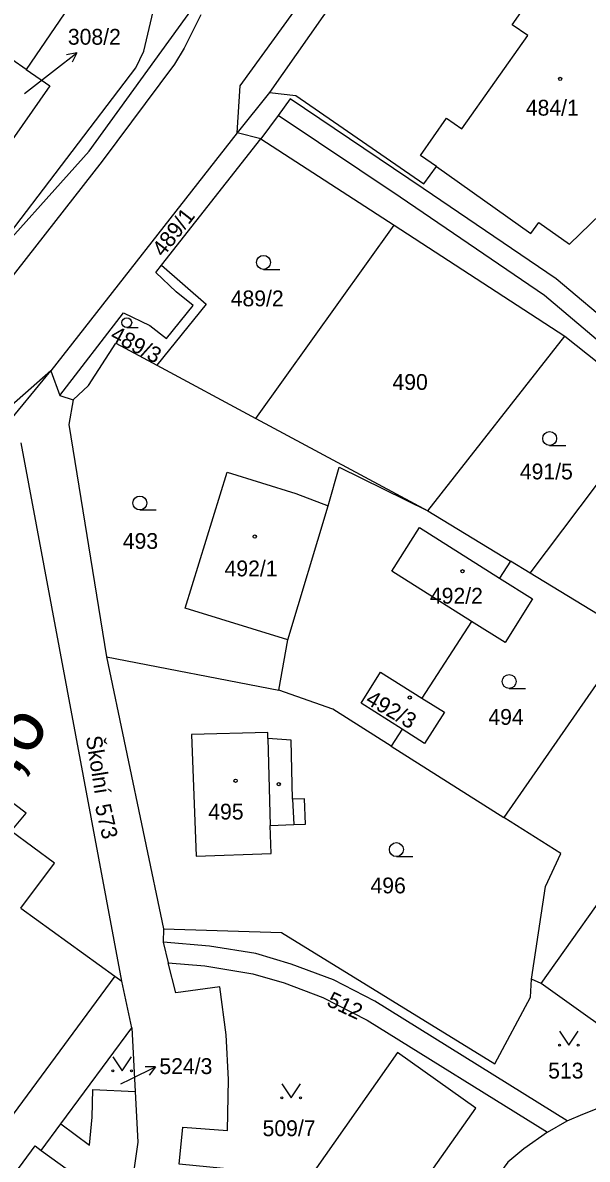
# Model space of a CAD drawing. Extents: x -558358 to -557517, y -1073786 to -1073189.
# Drawn here: x -558078.9 to -558018.3, y -1073467.9 to -1073345.8 of the extents above; entities that cross this region are included whole.
import ezdxf

# ---------------------------------------------------------------- set-up
doc = ezdxf.new("R2010")
doc.units = 0
for name, color, linetype in [('Hranice parcel', 7, 'Continuous'), ('Návěst místo trati', 7, 'Continuous'), ('Parcelní čísla', 7, 'Continuous'), ('Pop  PČ popisy', 7, 'Continuous'), ('Svazek obcí údolí Desné', 7, 'Continuous'), ('Vnitřní kresba', 7, 'Continuous'), ('Značky budov', 7, 'Continuous'), ('Značky kultur', 7, 'Continuous')]:
    doc.layers.add(name, color=color, linetype=linetype)

msp = doc.modelspace()

# ---------------------------------------------------------------- linework, layer by layer
at = {"layer": 'Hranice parcel'}
for p, q in [((-558028.41, -1073318.97), (-558052.39, -1073353.27)), ((-558055.85, -1073357.6), (-558055.56, -1073352.56)), ((-558052.39, -1073353.27), (-558055.85, -1073357.6)), ((-558051.46, -1073355.75), (-558053.32, -1073358.25)), ((-558055.85, -1073357.6), (-558075.89, -1073383.19)), ((-558063.99, -1073371.84), (-558053.32, -1073358.25)), ((-558053.32, -1073358.25), (-558055.85, -1073357.6)), ((-558053.32, -1073358.25), (-558038.99, -1073367.55)), ((-558053.86, -1073388.3), (-558038.99, -1073367.55)), ((-558038.99, -1073367.55), (-558020.67, -1073379.44)), ((-558035.4, -1073398.23), (-558020.67, -1073379.44)), ((-558064.49, -1073382.58), (-558053.86, -1073388.3)), ((-558075.89, -1073383.19), (-558086.19, -1073392.25)), ((-558081, -1073389.4), (-558075.89, -1073383.19)), ((-558075.89, -1073383.19), (-558074.9, -1073385.82)), ((-558074.9, -1073385.82), (-558073.48, -1073386.28)), ((-558024.42, -1073404.91), (-558011.29, -1073387.48)), ((-558053.86, -1073388.3), (-558035.4, -1073398.23)), ((-558068.26, -1073448.76), (-558079.07, -1073390.9)), ((-558035.4, -1073398.23), (-558026.52, -1073403.63)), ((-558039.27, -1073404.7), (-558036.29, -1073400)), ((-558036.29, -1073400), (-558027.69, -1073405.45)), ((-558030.69, -1073410.09), (-558039.27, -1073404.7)), ((-558026.52, -1073403.63), (-558027.69, -1073405.45)), ((-558024.42, -1073404.91), (-558026.52, -1073403.63)), ((-558027.69, -1073405.45), (-558024.15, -1073407.69)), ((-558013.61, -1073411.49), (-558024.42, -1073404.91)), ((-558024.15, -1073407.69), (-558027.08, -1073412.36)), ((-558030.69, -1073410.09), (-558036.02, -1073418.35)), ((-558027.08, -1073412.36), (-558030.69, -1073410.09)), ((-558013.61, -1073411.49), (-558027.22, -1073431.17)), ((-558069.9, -1073413.89), (-558063.79, -1073443.12)), ((-558069.9, -1073413.89), (-558051.38, -1073417.49)), ((-558042.56, -1073418.87), (-558040.48, -1073415.56)), ((-558040.48, -1073415.56), (-558036.02, -1073418.35)), ((-558038.16, -1073421.67), (-558042.56, -1073418.87)), ((-558036.02, -1073418.35), (-558033.6, -1073419.86)), ((-558033.6, -1073419.86), (-558035.74, -1073423.21)), ((-558038.16, -1073421.67), (-558039.34, -1073423.5)), ((-558035.74, -1073423.21), (-558038.16, -1073421.67)), ((-558039.34, -1073423.5), (-558027.22, -1073431.17)), ((-558079.09, -1073440.91), (-558069.01, -1073448.19)), ((-558063.79, -1073443.12), (-558063.8, -1073444.57)), ((-558063.8, -1073444.57), (-558063.26, -1073446.76)), ((-558069.01, -1073448.19), (-558068.26, -1073448.76)), ((-558023.22, -1073448.98), (-558024.27, -1073448.53)), ((-558067.19, -1073453.76), (-558068.26, -1073448.76)), ((-558074.8, -1073464.07), (-558067.19, -1073453.76)), ((-558067.19, -1073453.76), (-558066.82, -1073460.61)), ((-558071.37, -1073460.39), (-558066.82, -1073460.61)), ((-558076.9, -1073466.92), (-558074.8, -1073464.07)), ((-558074.8, -1073464.07), (-558071.72, -1073466.37)), ((-558022.54, -1073464.96), (-558020.42, -1073463.73)), ((-558086.45, -1073478.46), (-558077.57, -1073466.44)), ((-558077.57, -1073466.44), (-558076.9, -1073466.92)), ((-558076.9, -1073466.92), (-558072.2, -1073470.34))]:
    msp.add_line(p, q, dxfattribs=at)
for points in [[(-558055.56, -1073352.56), (-558041.67, -1073333.36), (-558032.81, -1073321.13)], [(-558034.47, -1073361.24), (-558036.19, -1073360.05), (-558033.38, -1073356.04), (-558031.73, -1073357.2), (-558024.67, -1073347.17), (-558026.34, -1073346.01), (-558023.11, -1073341.4), (-558021.44, -1073342.56), (-558017.77, -1073337.32)], [(-558083.8, -1073372.96), (-558071.77, -1073359.59), (-558059.92, -1073343.2), (-558058.64, -1073341.4)], [(-558059.76, -1073344.95), (-558061.55, -1073348.53), (-558062.6, -1073350.23), (-558070.37, -1073360.66), (-558089.91, -1073385.65), (-558114.04, -1073415.6), (-558119.93, -1073422.75), (-558120.74, -1073423.38), (-558121.71, -1073423.79), (-558122.74, -1073423.86)], [(-558052.39, -1073353.27), (-558049.55, -1073353.62), (-558035.82, -1073363.11), (-558034.47, -1073361.24)], [(-558015.07, -1073378.83), (-558021.62, -1073373.3), (-558035.88, -1073363.58), (-558050.18, -1073353.97), (-558051.46, -1073355.75)], [(-557997.16, -1073446.28), (-557996.18, -1073446.14), (-557992.37, -1073440.37), (-557993.13, -1073429.99), (-557993.58, -1073428.02), (-558004.25, -1073395), (-558005.55, -1073391.58), (-558006.57, -1073389.94), (-558009.69, -1073386.81), (-558015.69, -1073381.13), (-558022.86, -1073375.1), (-558038.38, -1073364.54), (-558051.46, -1073355.75)], [(-558034.47, -1073361.24), (-558024.32, -1073368.43), (-558023.47, -1073367.24), (-558020.17, -1073369.56), (-558013.44, -1073363.06)], [(-558074.9, -1073385.82), (-558068.06, -1073376.95), (-558065.25, -1073378.32), (-558063.46, -1073379.72), (-558060.6, -1073376.18), (-558062.42, -1073374.7), (-558064.61, -1073372.63), (-558063.99, -1073371.84)], [(-558063.99, -1073371.84), (-558059.19, -1073376.03), (-558064.49, -1073382.58)], [(-558073.48, -1073386.28), (-558071.82, -1073384.76), (-558068.89, -1073380.22), (-558064.49, -1073382.58)], [(-558020.67, -1073379.44), (-558013.21, -1073385.39), (-558011.29, -1073387.48)], [(-558073.48, -1073386.28), (-558073.96, -1073388.93), (-558069.9, -1073413.89)], [(-558051.38, -1073417.49), (-558050.42, -1073412.09), (-558061.44, -1073408.67), (-558056.95, -1073394.08), (-558049.56, -1073396.36), (-558046.09, -1073397.7), (-558044.91, -1073393.54), (-558035.4, -1073398.23)], [(-558079.09, -1073440.91), (-558075.49, -1073436.06), (-558080.13, -1073432.64), (-558078.53, -1073430.7), (-558082.12, -1073428.01), (-558083.47, -1073429.99), (-558090.26, -1073424.91), (-558087.3, -1073420.92), (-558091.08, -1073418.03), (-558093.98, -1073421.97), (-558100.23, -1073417.28)], [(-558039.34, -1073423.5), (-558045.61, -1073419.54), (-558051.38, -1073417.49)], [(-558049.8, -1073431.93), (-558048.54, -1073431.88), (-558048.64, -1073429.15), (-558049.91, -1073429.2), (-558050.08, -1073422.86), (-558052.56, -1073422.66), (-558052.57, -1073422.02), (-558060.76, -1073422.24), (-558060.26, -1073435.32), (-558052.21, -1073435.02), (-558052.32, -1073432.02), (-558049.8, -1073431.93)], [(-558023.22, -1073448.98), (-558004.82, -1073423.06), (-557993.94, -1073430.83), (-558002.36, -1073442.69), (-558001.05, -1073443.62)], [(-558024.27, -1073448.53), (-558022.77, -1073438.58), (-558021.1, -1073435.02), (-558027.22, -1073431.17)], [(-558063.79, -1073443.12), (-558051.12, -1073443.51), (-558028.21, -1073457.62), (-558024.35, -1073450.45), (-558024.27, -1073448.53)], [(-558020.42, -1073463.73), (-558041.1, -1073450.88), (-558045.53, -1073448.61), (-558050.06, -1073446.9), (-558053.87, -1073445.77), (-558058.84, -1073444.97), (-558063.8, -1073444.57)], [(-558002.62, -1073445.83), (-558003.93, -1073444.91), (-558012.33, -1073456.75), (-558023.22, -1073448.98)], [(-558066, -1073489.71), (-558065.83, -1073487.66), (-558063.93, -1073480.27), (-558059.28, -1073481.39), (-558058.41, -1073476.28), (-558057.32, -1073468.85), (-558062.09, -1073468.41), (-558061.69, -1073464.41), (-558056.9, -1073464.79), (-558056.8, -1073459.32), (-558057.06, -1073454.51), (-558057.72, -1073449.34), (-558062.47, -1073450), (-558063.26, -1073446.76)], [(-558063.26, -1073446.76), (-558059.34, -1073447.1), (-558054.18, -1073447.94), (-558050.82, -1073448.92), (-558046.65, -1073450.5), (-558041.92, -1073452.93), (-558022.54, -1073464.96)], [(-558069.01, -1073448.19), (-558089.39, -1073475.8), (-558089.17, -1073475.95), (-558090.09, -1073477.27), (-558100.29, -1073469.58), (-558095.61, -1073463.24)], [(-558020.42, -1073463.73), (-558018.76, -1073463.03), (-558003.4, -1073456.89), (-558000.84, -1073455.32), (-557998.53, -1073453.34), (-557997.26, -1073451.83), (-557996.12, -1073450.19)], [(-558035.54, -1073474.05), (-558034.14, -1073472.03), (-558036.08, -1073470.66), (-558030.24, -1073462.37), (-558038.66, -1073456.4), (-558058.9, -1073485.25), (-558050.49, -1073491.12), (-558038.98, -1073474.78), (-558037.01, -1073476.18)], [(-558066.82, -1073460.61), (-558066.53, -1073466.05), (-558068.98, -1073483.05), (-558070.17, -1073482.68), (-558072.89, -1073481.86), (-558073.42, -1073480.5), (-558073.98, -1073480.28)], [(-558071.72, -1073466.37), (-558071.45, -1073463.36), (-558071.37, -1073460.39)], [(-558022.54, -1073464.96), (-558025.08, -1073466.74), (-558026.8, -1073468.19), (-558032.65, -1073476.17)]]:
    msp.add_lwpolyline(points, dxfattribs=at)
at = {"layer": 'Pop  PČ popisy'}
for p, q in [((-558075.47, -1073350.88), (-558073.1, -1073349.03)), ((-558073.1, -1073349.03), (-558074.2, -1073349.25)), ((-558073.1, -1073349.03), (-558073.59, -1073350.04)), ((-558078.72, -1073353.4), (-558075.47, -1073350.88)), ((-558067.34, -1073459.26), (-558064.64, -1073457.94)), ((-558064.64, -1073457.94), (-558065.76, -1073457.93)), ((-558064.64, -1073457.94), (-558065.32, -1073458.83)), ((-558068.37, -1073459.77), (-558067.34, -1073459.26))]:
    msp.add_line(p, q, dxfattribs=at)
at = {"layer": 'Svazek obcí údolí Desné'}
for p, q in [((-558078.52, -1073350.81), (-558086.59, -1073345.2)), ((-558083.8, -1073372.96), (-558066.74, -1073350.64))]:
    msp.add_line(p, q, dxfattribs=at)
for points in [[(-558025.68, -1073189.92), (-558032.09, -1073212.63), (-558035.15, -1073249.33), (-558039.97, -1073265.01), (-558041.24, -1073272.26), (-558045.55, -1073290.79), (-558055.77, -1073312.33), (-558066.64, -1073329.29), (-558067.37, -1073328.67), (-558071.91, -1073335.47), (-558071.45, -1073339.78), (-558072.38, -1073341.74), (-558078.52, -1073350.81)], [(-558066.74, -1073350.64), (-558065.9, -1073348.86), (-558061.08, -1073328.44), (-558060.65, -1073327.54), (-558046.7, -1073313.29), (-558030.4, -1073296.27), (-558015.33, -1073274.48), (-558010.02, -1073266.4), (-558006.82, -1073259.79), (-558003.58, -1073251.39), (-558001.93, -1073245.63), (-558000.3, -1073233.47), (-558000.14, -1073230.76), (-558000.21, -1073228.76), (-558000.67, -1073225.31), (-558001.93, -1073222.03), (-558003.18, -1073219.55), (-558003.41, -1073218.32), (-558003.28, -1073217.31), (-558002.8, -1073216.38), (-558000.9, -1073214.81), (-557999.34, -1073213.91), (-558005.3, -1073194.99), (-558007.24, -1073189.96)], [(-558078.52, -1073350.81), (-558075.97, -1073352.58), (-558087.9, -1073369.62), (-558096.11, -1073380.17)]]:
    msp.add_lwpolyline(points, dxfattribs=at)
at = {"layer": 'Vnitřní kresba'}
for p, q in [((-558050.42, -1073412.09), (-558046.09, -1073397.7)), ((-558052.56, -1073422.66), (-558052.32, -1073432.02)), ((-558049.91, -1073429.2), (-558049.8, -1073431.93))]:
    msp.add_line(p, q, dxfattribs=at)
at = {"layer": 'Značky budov'}
for centre in [(-558021.18, -1073351.82), (-558053.98, -1073400.98), (-558031.67, -1073404.71), (-558037.33, -1073418.27), (-558056.04, -1073427.22), (-558051.4, -1073427.58)]:
    msp.add_circle(centre, 0.175, dxfattribs=at)
at = {"layer": 'Značky kultur'}
for p, q in [((-558053.04, -1073372.28), (-558051.29, -1073372.28)), ((-558067.72, -1073378.52), (-558066.5, -1073378.52)), ((-558022.31, -1073391.2), (-558020.56, -1073391.2)), ((-558066.32, -1073398.13), (-558064.57, -1073398.13)), ((-558026.66, -1073417.3), (-558024.91, -1073417.3)), ((-558038.77, -1073435.36), (-558037.02, -1073435.36))]:
    msp.add_line(p, q, dxfattribs=at)
for points in [[(-558021.24, -1073454.11), (-558020.24, -1073455.61), (-558019.24, -1073454.11)], [(-558069.21, -1073456.87), (-558068.21, -1073458.37), (-558067.21, -1073456.87)], [(-558051.07, -1073459.77), (-558050.07, -1073461.27), (-558049.07, -1073459.77)]]:
    msp.add_lwpolyline(points, dxfattribs=at)
for centre, radius in [((-558053.04, -1073371.53), 0.75), ((-558067.72, -1073378), 0.525), ((-558022.31, -1073390.45), 0.75), ((-558066.32, -1073397.38), 0.75), ((-558026.66, -1073416.55), 0.75), ((-558038.77, -1073434.61), 0.75), ((-558021.24, -1073455.61), 0.1), ((-558019.24, -1073455.61), 0.1), ((-558069.21, -1073458.37), 0.1), ((-558067.21, -1073458.37), 0.1), ((-558051.07, -1073461.27), 0.1), ((-558049.07, -1073461.27), 0.1)]:
    msp.add_circle(centre, radius, dxfattribs=at)

# ---------------------------------------------------------------- texts
at = {"layer": 'Návěst místo trati'}
msp.add_text('1,6', height=6, rotation=55.5139, dxfattribs=at).set_placement((-558082.19, -1073430.47))
at = {"layer": 'Parcelní čísla'}
for s, p in [('308/2', (-558074.05, -1073348.15)), ('484/1', (-558024.87, -1073355.77)), ('489/2', (-558056.56, -1073376.25)), ('490', (-558039.19, -1073385.23)), ('491/5', (-558025.51, -1073394.84)), ('493', (-558068.15, -1073402.31)), ('492/1', (-558057.22, -1073405.26)), ('492/2', (-558035.17, -1073408.19)), ('494', (-558028.89, -1073421.21)), ('495', (-558058.97, -1073431.38)), ('496', (-558041.55, -1073439.31)), ('524/3', (-558064.22, -1073458.72)), ('513', (-558022.47, -1073459.2)), ('509/7', (-558053.14, -1073465.39))]:
    msp.add_text(s, height=1.7, dxfattribs=at).set_placement(p)
for s, rotation, p in [('489/1', 52, (-558063.81, -1073371.04)), ('489/3', 332, (-558069.62, -1073379.77)), ('492/3', 330, (-558042.19, -1073418.87)), ('573', 283, (-558071.15, -1073429.91)), ('512', 335, (-558046.36, -1073451.33))]:
    msp.add_text(s, height=1.7, rotation=rotation, dxfattribs=at).set_placement(p)
at = {"layer": 'Pop  PČ popisy'}
msp.add_text('Školní', height=1.7, rotation=279, dxfattribs=at).set_placement((-558072.13, -1073422.5))

doc.saveas('drawing.dxf')
